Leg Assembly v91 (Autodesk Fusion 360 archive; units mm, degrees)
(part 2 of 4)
sketch "Sketch25" plane through (0, 0, 1.008) normal (0, 0, 1) x axis (-1, 0, 0)
  line L1 (-20.0076, 9.3042) -> (-16.55, 9.3042)
  line L2 (-20.0076, 2.9542) -> (-20.0076, 9.3042)
  line L3 (-16.55, 2.9542) -> (-20.0076, 2.9542)
  line L4 (-20.0076, -11.4458) -> (-17.255, -11.4458)
  line L5 (-20.0076, -17.7958) -> (-20.0076, -11.4458)
  line L6 (-17.255, -17.7958) -> (-20.0076, -17.7958)
  line L7 (-3.4928, -22.1208) -> (-13.668, -22.1208)
  line L8 (0.1537, -18.4744) -> (-3.4928, -22.1208)
  line L9 (0.1537, -10.7673) -> (0.1537, -18.4744)
  line L10 (-3.4928, -7.1208) -> (0.1537, -10.7673)
  line L11 (-13.668, -7.1208) -> (-3.4928, -7.1208)
  line L12 (-20.0076, -17.7958) -> (-17.255, -17.7958)
  line L13 (-20.0076, -11.4458) -> (-20.0076, -17.7958)
  line L14 (-17.255, -11.4458) -> (-20.0076, -11.4458)
  line L15 (-17.255, -17.7958) -> (-17.255, -11.4458)
  line L16 (-20.0076, 2.9542) -> (-16.55, 2.9542)
  line L17 (-20.0076, 9.3042) -> (-20.0076, 2.9542)
  line L18 (-16.55, 9.3042) -> (-20.0076, 9.3042)
  line L19 (-16.55, 2.9542) -> (-16.55, 9.3042)
  arc A1 centre (-8.3963, 6.1292) radius 8.75 clockwise from (-16.55, 9.3042) to (-16.55, 2.9542)
  arc A2 centre (-9.026, -14.6208) radius 8.8203 clockwise from (-17.255, -11.4458) to (-13.668, -7.1208)
  arc A3 centre (-9.026, -14.6208) radius 8.8203 clockwise from (-13.668, -22.1208) to (-17.255, -17.7958)
  point P10 (-20.0076, -11.4458)
  point P20 (-20.0076, -11.4458)
  point P12 (-17.255, -17.7958)
  point P18 (-17.255, -17.7958)
  point P5 (-20.0076, 9.3042)
  point P24 (-20.0076, 9.3042)
  point P2 (-16.55, 2.9542)
  point P22 (-16.55, 2.9542)
  horizontal L12
  vertical L13
  horizontal L14
  vertical L15
  coincident P10 P20
  coincident P12 P18
  horizontal L16
  vertical L17
  horizontal L18
  vertical L19
  coincident P5 P24
  coincident P2 P22
extrude "Extrude10" cut sketch "Sketch25" profile of L1 L2 L3 L16 L17 L18 L19 against normal blind 8.89
extrude "Extrude11" cut sketch "Sketch25" profile of L4 L5 L6 L12 L13 L14 L15 distance 11.43
copy_paste "CutPaste1"
remove_instance "RemoveInstance8"
remove_instance "RemoveInstance9"
mirror_component "MirrorComponent2"
derived_instance "DerivedInstance2"
position "Position4"
position "Position5"
position "Position6"
position "Position7"
sketch "main sketch" plane through (0, -27.2, 0) normal (0, -1, 0) x axis (1, 0, 0)
  line L1 (-18.7031, 75.8108) -> (12.2732, 75.8108)
  line L2 (-3.2149, -51.1892) -> (-3.2149, 75.8108)
  line L3 (-52.3824, 37.6979) -> (-20.6556, 77.3722)
  line L4 (-16.7506, 74.2495) -> (-48.4774, 34.5752)
  line L5 (-50.4299, 36.1365) -> (-18.7031, 75.8108)
  line L6 (-5.3332, -40.5169) -> (-52.5482, 34.8088)
  line L7 (-48.3116, 37.4643) -> (-1.0967, -37.8614)
  line L8 (-3.2149, -39.1892) -> (-50.4299, 36.1365)
  line L9 (-51.9387, 49.1154) -> (-56.8979, 53.0812)
  line L10 (-25.9057, 52.0131) -> (-51.9387, 49.1154)
  line L11 (-130.2149, -51.1892) -> (-130.2149, 75.8108)
  line L12 (-130.2149, 75.8108) -> (-3.2149, 75.8108)
  line L13 (-130.2149, -51.1892) -> (-3.2149, -51.1892)
  line L14 (42.0475, 34.5752) -> (10.3208, 74.2495)
  line L15 (14.2257, 77.3722) -> (45.9525, 37.6979)
  line L16 (44, 36.1365) -> (12.2732, 75.8108)
  line L17 (-5.3332, -37.8614) -> (41.8817, 37.4643)
  line L18 (46.1183, 34.8088) -> (-1.0967, -40.5169)
  line L19 (-3.2149, -39.1892) -> (44, 36.1365)
  line L20 (45.5088, 49.1154) -> (19.4758, 52.0131)
  line L21 (50.4681, 53.0812) -> (45.5088, 49.1154)
  circle C1 centre (12.2732, 75.8108) radius 1.5
  circle C2 centre (-18.7031, 75.8108) radius 1.5
  circle C3 centre (-18.7031, 75.8108) radius 14
  circle C4 centre (-50.4299, 36.1365) radius 11.5
  arc A1 centre (-50.4299, 36.1365) radius 2.5 clockwise from (-48.4774, 34.5752) to (-52.3824, 37.6979)
  arc A2 centre (-18.7031, 75.8108) radius 2.5 clockwise from (-20.6556, 77.3722) to (-16.7506, 74.2495)
  arc A3 centre (12.7387, 22.1428) radius 76.2 clockwise from (-61.6577, 38.6238) to (-25.78, 87.8905)
  arc A4 centre (29.1955, -0.6206) radius 76.2 clockwise from (-39.9887, 31.3166) to (-11.2687, 63.9479)
  arc A5 centre (-3.2149, -39.1892) radius 2.5 clockwise from (-1.0967, -37.8614) to (-5.3332, -40.5169)
  arc A6 centre (-50.4299, 36.1365) radius 2.5 clockwise from (-52.5482, 34.8088) to (-48.3116, 37.4643)
  circle C5 centre (-3.2149, -39.1892) radius 9
  arc A7 centre (129.3236, 102.7516) radius 203.2 clockwise from (-9.3573, -45.7673) to (-61.2132, 32.1403)
  arc A8 centre (153.1884, 104.2222) radius 203.2 clockwise from (3.4186, -33.1067) to (-39.5235, 39.7834)
  circle C6 centre (12.2732, 75.8108) radius 14
  circle C7 centre (44, 36.1365) radius 11.5
  arc A9 centre (44, 36.1365) radius 2.5 clockwise from (45.9525, 37.6979) to (42.0475, 34.5752)
  arc A10 centre (12.2732, 75.8108) radius 2.5 clockwise from (10.3208, 74.2495) to (14.2257, 77.3722)
  arc A11 centre (-3.2149, -39.1892) radius 2.5 clockwise from (-1.0967, -40.5169) to (-5.3332, -37.8614)
  arc A12 centre (44, 36.1365) radius 2.5 clockwise from (41.8817, 37.4643) to (46.1183, 34.8088)
  arc A13 centre (-19.1685, 22.1428) radius 76.2 clockwise from (19.3502, 87.8905) to (55.2278, 38.6238)
  arc A14 centre (-35.6254, -0.6206) radius 76.2 clockwise from (4.8389, 63.9479) to (33.5588, 31.3166)
  arc A15 centre (-135.7535, 102.7516) radius 203.2 clockwise from (54.7833, 32.1403) to (2.9274, -45.7673)
  arc A16 centre (-159.6183, 104.2222) radius 203.2 clockwise from (33.0936, 39.7834) to (-9.8485, -33.1067)
  point P2 (12.2732, 75.8108)
  point P5 (12.2732, 75.8108)
  point P4 (-18.7031, 75.8108)
  point P6 (-18.7031, 75.8108)
  point P7 (-3.2149, 75.8108)
  point P14 (-18.7031, 75.8108)
  point P9 (-50.4299, 36.1365)
  point P15 (-50.4299, 36.1365)
  point P20 (-39.9887, 31.3166)
  point P19 (-11.2687, 63.9479)
  point P17 (-25.78, 87.8905)
  point P16 (-61.6577, 38.6238)
  point P26 (-50.4299, 36.1365)
  point P30 (-9.3573, -45.7673)
  point P29 (-61.2132, 32.1403)
  point P33 (3.4186, -33.1067)
  point P32 (-39.5235, 39.7834)
  point P35 (-56.8979, 53.0812)
  point P37 (-25.9057, 52.0131)
  point P40 (-130.2149, 75.8108)
  point P38 (-130.2149, 75.8108)
  point P41 (-130.2149, -51.1892)
  point P39 (-130.2149, -51.1892)
  point P48 (12.2732, 75.8108)
  point P27 (-3.2149, -39.1892)
  point P55 (-3.2149, -39.1892)
  point P49 (44, 36.1365)
  point P54 (44, 36.1365)
  point P43 (44, 36.1365)
  point P56 (19.3502, 87.8905)
  point P59 (4.8389, 63.9479)
  point P57 (55.2278, 38.6238)
  point P60 (33.5588, 31.3166)
  point P65 (33.0936, 39.7834)
  point P62 (54.7833, 32.1403)
  point P63 (2.9274, -45.7673)
  point P66 (-9.8485, -33.1067)
  point P68 (19.4758, 52.0131)
  point P70 (50.4681, 53.0812)
  point P36 (-51.9387, 49.1154)
  point P28 (-3.2149, -39.1892)
  point P69 (45.5088, 49.1154)
  concentric C2 C3
  coincident P2 P5
  coincident P4 P6
  midpoint L1 P7
  perpendicular L1 L2
  tangent L3 A1
  tangent A1 L4
  parallel L3 L4
  tangent L4 A2
  tangent L3 A2
  coincident P4 P14
  coincident P9 P15
  tangent C3 A3
  tangent C4 A3
  coincident C4 P20
  coincident C3 P19
  tangent C3 A4
  tangent C4 A4
  coincident C3 P17
  coincident C4 P16
  tangent L6 A5
  tangent A5 L7
  parallel L6 L7
  tangent L7 A6
  tangent L6 A6
  coincident P9 P26
  concentric A5 C5
  coincident C5 P30
  coincident C4 P29
  coincident C5 P33
  coincident C4 P32
  tangent C5 A8
  tangent C5 A7
  tangent C4 A8
  tangent C4 A7
  coincident A3 P35
  coincident A4 P37
  parallel L2 L11
  coincident L11 P40
  perpendicular L11 L12
  coincident P38 L12
  coincident L11 P41
  perpendicular L11 L13
  coincident P39 P41
  concentric C1 C6
  tangent L14 A9
  tangent A9 L15
  parallel L14 L15
  tangent L15 A10
  tangent L14 A10
  coincident P2 P48
  tangent L17 A11
  tangent A11 L18
  parallel L17 L18
  tangent L18 A12
  tangent L17 A12
  coincident P27 P55
  coincident P49 P54
  coincident P43 P54
  tangent C6 A13
  tangent C7 A13
  tangent C7 A14
  tangent C6 A14
  coincident C6 P56
  coincident C6 P59
  coincident C7 P57
  coincident C7 P60
  tangent C7 A16
  tangent C5 A16
  tangent C5 A15
  tangent C7 A15
  coincident C7 P65
  coincident C7 P62
  coincident C5 P63
  coincident C5 P66
  coincident A14 P68
  coincident A13 P70
  dimension "d55" distance L3 L4 = 5
  dimension "d57" distance P14 P15 = 50.8
  dimension "d58" radius A3 = 76.2
  dimension "d69" radius A4 = 76.2 (= "d58")
  dimension "d123" diameter C3 = 28
  dimension "d124" diameter C4 = 23
  dimension "d125" distance P26 P27 = 88.9
  dimension "d126" distance L6 L7 = 5 (= "d55")
  dimension "d127" diameter C5 = 18
  dimension "d128" radius A7 = 203.2 (= "d129")
  dimension "d129" radius A8 = 203.2
  dimension "d142" distance P35 P36 = 6.35
  dimension "d143" angle L9 L10 = 135
  dimension "d144" angle L5 L9 = 90
  dimension "d145" distance P36 P37 = 26.1938 (= "1 in + ( ( 1 / 32 ) * 1 in )")
  dimension "d146" distance P7 P40 = 127
  dimension "d147" distance P28 L11 = 127 (= "5 in + X")
  dimension "d186" distance P28 L12 = 115 (= "Linear Dimension-10")
  dimension "d201" distance P38 P39 = 127
  dimension "d230" distance L14 L15 = 5
  dimension "d231" diameter A11 = 5
  dimension "d232" distance P54 P55 = 88.9 (= "d125")
  dimension "d233" distance P48 P49 = 50.8 (= "d57")
  dimension "d234" diameter C7 = 23 (= "d124")
  dimension "d235" diameter C6 = 28 (= "d123")
  dimension "d236" radius A13 = 76.2 (= "d58")
  dimension "d237" radius A14 = 76.2 (= "d58")
  dimension "d238" radius A15 = 203.2 (= "d128")
  dimension "d239" radius A16 = 203.2 (= "d128")
  dimension "d245" angle L20 L21 = 135 (= "d143")
  dimension "d246" angle L16 L21 = 90 (= "d144")
  dimension "d247" distance P69 P70 = 6.35 (= "d142")
  dimension "d248" distance P68 P69 = 26.1938 (= "d145")
work_plane "WorkPlane1" PathDistance 0.5
copy_paste "CutPaste1"
copy_paste "CutPaste2"
copy_paste "CutPaste1"
extrude "Extrude1" new body sketch "main sketch" profile of C3 C4 A3 A4 A8 L9 L10 along normal blind 20.05 (= "0.75 in + gapfit1")
extrude "Extrude3" new body sketch "main sketch" profile of C4 A4 C5 A7 A8 A16 blind 6.35 from offset 6.85 (= "( 0.5 in + gapfit1 ) / 2")
extrude "Extrude4" new body sketch "main sketch" profile of C6 C7 A13 A14 A16 L20 L21 along normal blind 20.05 (= "0.75 in + gapfit1")
extrude "Extrude5" new body sketch "main sketch" profile of C5 A8 C7 A14 A15 A16 blind 6.35 from offset 6.85 (= "( 0.5 in + gapfit1 ) / 2")
extrude "Extrude6" cut sketch "main sketch" profile of C4 A3 A4 A8 L9 L10 C7 A13 A14 A16 L20 L21 blind 6.35 from offset 6.85 (= "( 0.5 in + gapfit1 ) / 2")
work_plane "WorkPlane3" AlongDistance 6.85 (= "0.25 in + gapfit2")
align "Align5"
align "Align6"
sketch "Sketch12" plane through (0, -20.35, 0) normal (0, 1, 0) x axis (-1, 0, 0)
  arc A1 centre (-12.7387, 22.1428) radius 76.2 clockwise from (25.78, 87.8905) to (61.6577, 38.6238)
  arc A2 centre (18.7031, 75.8108) radius 14 clockwise from (11.2687, 63.9479) to (25.78, 87.8905)
  arc A3 centre (-29.1955, -0.6206) radius 76.2 clockwise from (11.2687, 63.9479) to (39.9887, 31.3166)
  arc A4 centre (50.4299, 36.1365) radius 11.5 clockwise from (61.6577, 38.6238) to (39.9887, 31.3166)
  circle C1 centre (18.7031, 75.8108) radius 14
  point P3 (25.78, 87.8905)
  concentric A2 C1
  coincident P3 C1
extrude "Extrude31" cut sketch "Sketch12" profile of A2 C1 against normal blind 6.85 (magnitude of "-0.25 in - gapfit2")
fillet "Fillet2" radius 3.175
extrude "Extrude21" cut of existing geometry blind -0.5 (= "-gapfit1 / 2")
extrude "Extrude22" cut of existing geometry blind -0.5 (= "-gapfit1 / 2")
extrude "Extrude23" cut of existing geometry blind -0.5 (= "-gapfit1 / 2")
extrude "Extrude24" cut of existing geometry blind -0.5 (= "-gapfit1 / 2")
component_from_bodies "Body->Comp1"
component_from_bodies "Body->Comp2"
component_from_bodies "Body->Comp3"
component_from_bodies "Body->Comp4"
copy_paste "CutPaste1"
copy_paste "CutPaste2"
copy_paste "CutPaste3"
copy_paste "CutPaste4"
sketch "Sketch10" plane through (0, -33.55, 0) normal (0, -1, 0) x axis (1, 0, 0)
  line L1 (-3.2149, -39.1892) -> (-50.4299, 36.1365)
  line L2 (-3.2149, -39.1892) -> (44, 36.1365)
  line L3 (-22.3639, -32.4561) -> (-5.9307, -22.1556)
  line L4 (-0.4992, -22.1556) -> (15.9341, -32.4561)
  line L5 (-54.0229, 15.1486) -> (-34.8377, 27.1741)
  line L6 (47.593, 15.1486) -> (28.4078, 27.1741)
  line L7 (-28.622, 4.84) -> (-50.611, 17.2872)
  line L8 (-32.9107, -12.8368) -> (-28.622, 4.84)
  line L9 (-16.9311, -14.0621) -> (-32.9107, -12.8368)
  line L10 (-18.9252, -30.3007) -> (-16.9311, -14.0621)
  line L11 (22.1921, 4.84) -> (44.1811, 17.2872)
  line L12 (26.4808, -12.8368) -> (22.1921, 4.84)
  line L13 (10.5012, -14.0621) -> (26.4808, -12.8368)
  line L14 (12.4954, -30.3007) -> (10.5012, -14.0621)
  arc A1 centre (153.1884, 104.2222) radius 203.2 clockwise from (3.4186, -33.1067) to (-39.5235, 39.7834)
  arc A2 centre (129.3236, 102.7516) radius 203.2 clockwise from (-9.3573, -45.7673) to (-61.2132, 32.1403)
  circle C1 centre (-50.4299, 36.1365) radius 11.5
  circle C2 centre (-3.2149, -39.1892) radius 9
  arc A3 centre (-135.7535, 102.7516) radius 203.2 clockwise from (54.7833, 32.1403) to (2.9274, -45.7673)
  arc A4 centre (-159.6183, 104.2222) radius 203.2 clockwise from (33.0936, 39.7834) to (-9.8485, -33.1067)
  circle C3 centre (44, 36.1365) radius 11.5
  arc A5 centre (153.1884, 104.2222) radius 207.2 clockwise from (0.4703, -35.81) to (-43.317, 38.5149)
  arc A6 centre (129.3236, 102.7516) radius 199.2 clockwise from (-6.6274, -42.8437) to (-57.4625, 33.5303)
  arc A7 centre (-159.6183, 104.2222) radius 207.2 clockwise from (36.8871, 38.5149) to (-6.9002, -35.81)
  arc A8 centre (-135.7535, 102.7516) radius 199.2 clockwise from (51.0326, 33.5303) to (0.1975, -42.8437)
  point P21 (-5.9307, -22.1556)
  point P22 (-22.3639, -32.4561)
  point P23 (15.9341, -32.4561)
  point P24 (-0.4992, -22.1556)
  point P25 (-34.8377, 27.1741)
  point P26 (-54.0229, 15.1486)
  point P27 (28.4078, 27.1741)
  point P28 (47.593, 15.1486)
  point P41 (-50.611, 17.2872)
  point P42 (-28.622, 4.84)
  point P43 (-32.9107, -12.8368)
  point P44 (-16.9311, -14.0621)
  point P45 (-18.9252, -30.3007)
  point P46 (44.1811, 17.2872)
  point P47 (22.1921, 4.84)
  point P48 (26.4808, -12.8368)
  point P49 (10.5012, -14.0621)
  point P50 (12.4954, -30.3007)
  point P18 (-3.2149, -39.1892)
  point P20 (-3.2149, -39.1892)
  point P8 (-50.4299, 36.1365)
  point P16 (44, 36.1365)
  coincident A1 P21
  coincident A2 P22
  perpendicular L1 L3
  coincident A3 P23
  coincident A4 P24
  perpendicular L2 L4
  coincident A1 P25
  coincident A2 P26
  coincident A4 P27
  coincident A3 P28
  perpendicular L2 L6
  perpendicular L1 L5
  coincident A6 P41
  coincident L5 P41
  coincident A5 P42
  coincident A6 P43
  coincident A5 P44
  coincident L3 P45
  coincident A6 P45
  coincident L6 P46
  coincident A8 P46
  coincident A7 P47
  coincident A8 P48
  coincident A7 P49
  coincident A8 P50
  coincident L4 P50
  dimension "d338" distance P18 L3 = 15.875
  dimension "d339" distance P20 L4 = 15.875 (= "d338")
  dimension "d340" distance P8 L5 = 15.875
  dimension "d341" distance P16 L6 = 15.875 (= "d340")
  dimension "d342" = 4
  dimension "d343" = -4
  dimension "d344" = 4
  dimension "d345" = -4
  dimension "d346" distance L5 P42 = 22.225
  dimension "d347" distance L5 P43 = 34.925
  dimension "d348" distance L5 P44 = 44.45
  dimension "d349" distance L6 P47 = 22.225 (= "d346")
  dimension "d350" distance L6 P48 = 34.925 (= "d347")
  dimension "d351" distance L6 P49 = 44.45 (= "d348")
extrude "Extrude1" cut sketch "Sketch10" profile of L3 L4 L5 L6 A5 A6 A7 A8 L7 L8 L9 L10 L11 L12 L13 L14 distance -119.38
web "Web1" Thickness 4
sketch "Sketch11" plane through (0, -40.4, 0) normal (0, -1, 0) x axis (1, 0, 0)
  line L1 (10.5012, -14.0621) -> (26.4808, -12.8368)
  line L2 (12.4954, -30.3007) -> (10.5012, -14.0621)
  line L3 (26.4808, -12.8368) -> (22.1921, 4.84)
  line L4 (22.1921, 4.84) -> (44.1811, 17.2872)
  line L5 (44.1811, 17.2872) -> (31.8462, 25.0189)
  line L6 (2.9107, -24.293) -> (12.4954, -30.3007)
  arc A1 centre (-135.7535, 102.7516) radius 203.2 clockwise from (54.7833, 32.1403) to (2.9274, -45.7673)
  arc A2 centre (44, 36.1365) radius 11.5 clockwise from (33.0936, 39.7834) to (54.7833, 32.1403)
  arc A3 centre (-159.6183, 104.2222) radius 203.2 clockwise from (33.0936, 39.7834) to (-9.8485, -33.1067)
  arc A4 centre (-3.2149, -39.1892) radius 9 clockwise from (2.9274, -45.7673) to (-9.8485, -33.1067)
  arc A5 centre (-135.7535, 102.7516) radius 199.2 clockwise from (44.1811, 17.2872) to (12.4954, -30.3007)
  arc A6 centre (-159.6183, 104.2222) radius 207.2 clockwise from (31.8462, 25.0189) to (2.9107, -24.293)
web "Web1" Thickness 4
fillet "Fillet2" radius 1.5
chamfer "Chamfer1" distance 1.5875 (= "( 1 / 16 ) * 1 in")
sketch "Sketch13" plane through (0, 24.8582, 0) normal (0, 1, 0) x axis (-1, 0, 0)
  line L1 (37.9202, 66.7891) -> (25.2712, 55.623)
  line L2 (3.0497, 111.0882) -> (38.1993, 71.2706)
  line L3 (-14.0808, 100.2011) -> (-1.4317, 111.3672)
  line L4 (40.3005, 68.8903) -> (0.9485, 113.4684)
  line L5 (5.4814, 38.1532) -> (40.3005, 68.8903)
  line L6 (-33.8706, 82.7314) -> (5.4814, 38.1532)
  line L7 (0.9485, 113.4684) -> (-33.8706, 82.7314)
  line L8 (38.1993, 71.2706) -> (3.0497, 111.0882)
  line L9 (-1.4317, 111.3672) -> (-14.0808, 100.2011)
  line L10 (25.2712, 55.623) -> (37.9202, 66.7891)
  line L11 (-31.7694, 80.3511) -> (3.3802, 40.5335)
  line L12 (7.8616, 40.2544) -> (20.5107, 51.4206)
  line L13 (-18.8413, 95.9987) -> (-31.4904, 84.8326)
  line L14 (-34.5763, 82.7753) -> (5.4374, 37.4475)
  line L15 (0.9924, 114.1742) -> (-34.5763, 82.7753)
  line L16 (41.0062, 68.8464) -> (0.9924, 114.1742)
  line L17 (5.4374, 37.4475) -> (41.0062, 68.8464)
  line L18 (1.411, 120.8964) -> (-41.2985, 83.1939)
  line L19 (47.7284, 68.4278) -> (1.411, 120.8964)
  line L20 (5.0189, 30.7253) -> (47.7284, 68.4278)
  line L21 (-41.2985, 83.1939) -> (5.0189, 30.7253)
  line L22 (47.7284, 68.4278) -> (1.411, 120.8964)
  line L23 (57.2494, 76.8326) -> (47.7284, 68.4278)
  line L24 (10.932, 129.3012) -> (57.2494, 76.8326)
  line L25 (1.411, 120.8964) -> (10.932, 129.3012)
  line L26 (5.0189, 30.7253) -> (-41.2985, 83.1939)
  line L27 (-4.5021, 22.3205) -> (5.0189, 30.7253)
  line L28 (-50.8195, 74.7891) -> (-4.5021, 22.3205)
  line L29 (-41.2985, 83.1939) -> (-50.8195, 74.7891)
  arc A1 centre (-11.9796, 97.8209) radius 3.175 clockwise from (-14.3599, 95.7197) to (-14.0808, 100.2011)
  arc A2 centre (23.17, 58.0032) radius 3.175 clockwise from (25.2712, 55.623) to (20.7897, 55.902)
  point P19 (-1.4317, 111.3672)
  point P26 (-31.4904, 84.8326)
  point P6 (25.2712, 55.623)
  point P22 (3.3802, 40.5335)
  point P17 (38.1993, 71.2706)
  perpendicular L4 L5
  parallel L4 L6
  parallel L5 L7
  coincident L7 P19
  coincident L7 P26
  coincident P6 L5
  coincident L6 P22
  coincident L4 P17
  perpendicular L22 L23
  parallel L22 L24
  parallel L23 L25
  perpendicular L26 L27
  parallel L26 L28
  parallel L27 L29
  dimension "d373" = -0.5 (= "-gapfit3")
  dimension "d374" = -5.2625 (= "-gapfit3 - 0.1875 in")
  dimension "d394" distance L22 L24 = 12.7
  dimension "d395" distance L21 L28 = 12.7
extrude "Extrude32" new body sketch "Sketch13" profile of L14 L15 L16 L17 L18 L19 L20 L21 against normal blind 32.8676
fillet "Fillet3" radius 3.675 (= "0.125 in + gapfit3")
copy_paste_bodies "CutPasteBodies1"
component_from_bodies "Body->Comp1"
fillet "Fillet1" radius 8.4375 (= "0.125 in + 0.1875 in + gapfit3")
sketch "Sketch14" plane through (-18.0647, 0, 15.9469) normal (0.7497, 0, -0.6618) x axis (0, 1, 0)
  line L1 (16.8832, 68.1316) -> (16.8832, 61.7816)
  line L2 (18.032, 47.6316) -> (18.032, 41.2816)
  line L3 (14.8582, 41.2816) -> (18.032, 41.2816)
  line L4 (16.8832, 68.1316) -> (14.8582, 68.1316)
  line L5 (20.0319, 70.1316) -> (-8.0094, 70.1316)
  line L6 (20.0319, 39.2816) -> (20.0319, 70.1316)
  line L7 (-8.0094, 39.2816) -> (20.0319, 39.2816)
  line L8 (-8.0094, 70.1316) -> (-8.0094, 39.2816)
  line L9 (-8.0094, 81.2628) -> (-8.0094, 28.1503)
  horizontal L5
  vertical L6
  horizontal L7
  vertical L8
  collinear L8 L9
  dimension "d385" distance L2 L6 = 2
  dimension "d386" distance L4 L5 = 2
  dimension "d387" distance L3 L7 = 2
copy_paste "CutPaste4"
extrude "Extrude1" cut sketch "Sketch14" profile of L5 L6 L7 L8 against normal blind 91.44
sketch "Sketch15" plane through (59.3633, 0, 67.247) normal (0.6618, 0, 0.7497) x axis (0, 1, 0)
  line L1 (-8.0094, 72.6289) -> (-8.0094, 32.5339)
  line L2 (20.032, 61.4977) -> (-8.0094, 61.4977)
  line L3 (20.032, 43.6652) -> (20.032, 61.4977)
  line L4 (-8.0094, 43.6652) -> (20.032, 43.6652)
  line L5 (-8.0094, 61.4977) -> (-8.0094, 43.6652)
  line L6 (24.8582, 24.0964) -> (-8.0094, 24.0964)
  line L7 (-8.0094, 81.0664) -> (24.8582, 81.0664)
  point P4 (-8.0094, 61.4977)
  point P5 (20.032, 61.4977)
  horizontal L2
  vertical L3
  horizontal L4
  vertical L5
  coincident L1 P4
  dimension "d401" distance P4 P5 = 28.0414
  dimension "d403" distance L4 L6 = 19.5688
  dimension "d404" distance L2 L7 = 19.5688
extrude "Extrude3" cut sketch "Sketch15" profile of L1 L2 L3 L4 L5 against normal blind 180.34
fillet "Fillet2" radius 3.175
extrude "Extrude2" add sketch "Sketch13" profile of L4 L5 L6 L7 L8 L9 L10 L12 L13 L14 L15 L16 L17 L18 L19 L20 L21 L22 L23 L24 L25 L26 L27 L28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 along normal blind 4.7625
fillet "Fillet4" radius 12.7
work_plane "WorkPlane8"
offset_faces "OffsetFaces1" distance -9.9385
sketch "Sketch16" plane through (0, 0, 0) normal (0, 1, 0) x axis (1, 0, 0)
  circle C1 centre (12.2732, -75.8108) radius 10
  circle C2 centre (12.2732, -75.8108) radius 1.5
  circle C3 centre (12.2732, -68.8108) radius 1.5
  circle C4 centre (12.2732, -82.8108) radius 1.5
  circle C5 centre (19.2732, -75.8108) radius 1.5
  circle C6 centre (5.2732, -75.8108) radius 1.5
  circle C7 centre (-18.7031, -75.8108) radius 10
  circle C8 centre (-18.7031, -75.8108) radius 1.5
  circle C9 centre (-25.7031, -75.8108) radius 1.5
  circle C10 centre (-11.7031, -75.8108) radius 1.5
  circle C11 centre (-18.7031, -82.8108) radius 1.5
  circle C12 centre (-18.7031, -68.8108) radius 1.5
base_feature "Base Feature1"
base_feature "Base Feature1"
hole "Hole4" HoleDepth 93.98 HoleDiameter 3.5 (= "m3_diam") TipAngle 180
align "Align1"
sketch "Sketch17" plane through (0, -47.25, 0) normal (0, -1, 0) x axis (1, 0, 0)
  line L1 (-25.7031, 79.2172) -> (-22.7531, 77.514)
  line L2 (-28.6531, 77.514) -> (-25.7031, 79.2172)
  line L3 (-28.6531, 74.1077) -> (-28.6531, 77.514)
  line L4 (-25.7031, 72.4045) -> (-28.6531, 74.1077)
  line L5 (-22.7531, 74.1077) -> (-25.7031, 72.4045)
  line L6 (-22.7531, 77.514) -> (-22.7531, 74.1077)
  line L7 (-25.7031, 79.2172) -> (-25.7031, 75.8108)
  line L8 (5.2732, 79.2172) -> (5.2732, 75.8108)
  line L9 (2.3232, 77.514) -> (5.2732, 79.2172)
  line L10 (2.3232, 74.1077) -> (2.3232, 77.514)
  line L11 (5.2732, 72.4045) -> (2.3232, 74.1077)
  line L12 (8.2232, 74.1077) -> (5.2732, 72.4045)
  line L13 (8.2232, 77.514) -> (8.2232, 74.1077)
  line L14 (5.2732, 79.2172) -> (8.2232, 77.514)
  circle C1 centre (12.2732, 82.8108) radius 1.75
  circle C2 centre (12.2732, 68.8108) radius 1.75
  circle C3 centre (19.2732, 75.8108) radius 1.75
  point P5 (-25.7031, 75.8108)
  point P13 (-25.7031, 75.8108)
  point P14 (-25.7031, 75.8108)
  point P8 (-25.7031, 79.2172)
  point P15 (-25.7031, 79.2172)
  point P6 (5.2732, 75.8108)
  point P16 (5.2732, 75.8108)
  point P24 (5.2732, 75.8108)
  point P17 (5.2732, 79.2172)
  point P18 (5.2732, 79.2172)
  coincident P5 P13
  coincident P5 P14
  vertical L7
  coincident P8 L7
  coincident P8 P15
  coincident P6 P16
  vertical L8
  coincident P16 P24
  coincident P17 P18
  dimension "d438" distance L3 L6 = 5.9 (= "m3_locknut_width")
  dimension "d439" distance L10 L13 = 5.9 (= "m3_locknut_width")
extrude "Extrude1" cut sketch "Sketch17" profile of L9 L10 L11 L12 L13 L14 against normal blind 4
extrude "Extrude1" sketch "Sketch17" profile of L1 L2 L3 L4 L5 L6 blind -4
circular_pattern "C-Pattern1" TotalAngle 360
circular_pattern "C-Pattern1" TotalAngle 360
align "Align1"
circular_pattern "C-Pattern1" TotalAngle 360
circular_pattern "C-Pattern2" TotalAngle 360
copy_paste_bodies "CopyPasteBodies1"
move "Move4"
align "Align7"
offset_faces "OffsetFaces3" distance 4
copy_paste_bodies "CopyPasteBodies2"
move "Move5"
align "Align8"
offset_faces "OffsetFaces6" distance 5
circular_pattern "C-Pattern1" TotalAngle 360
component_from_bodies "Body->Comp7"
copy_paste_bodies "CutPasteBodies1"
copy_paste_bodies "CutPasteBodies1"
copy_paste "CutPaste1"
extrude "Extrude5" add of existing geometry blind 1.5875 (= "( 1 / 16 ) * 1 in")
copy_paste_bodies "CopyPasteBodies3"
move "Move6"
align "Align9"
copy_paste_bodies "CopyPasteBodies4"
move "Move7"
align "Align10"
offset_faces "OffsetFaces4" distance 9
copy_paste_bodies "CutPasteBodies2"
component_from_bodies "Body->Comp8"
copy_paste "CutPaste2"
hole "Hole1" HoleDepth 93.98 HoleDiameter 3.5 (= "m3_diam") TipAngle 180
copy_paste_bodies "CopyPasteBodies5"
move "Move8"
align "Align11"
offset_faces "OffsetFaces5" distance 9
copy_paste_bodies "CopyPasteBodies6"
move "Move9"
align "Align12"
copy_paste_bodies "CopyPasteBodies7"
move "Move10"
align "Align13"
copy_paste_bodies "CopyPasteBodies8"
move "Move11"
align "Align14"
copy_paste_bodies "CutPasteBodies1"
copy_paste_bodies "CutPasteBodies2"
copy_paste_bodies "CutPasteBodies1"
copy_paste_bodies "CutPasteBodies2"
hole "Hole2" HoleDepth 93.98 HoleDiameter 3.5 (= "m3_diam") TipAngle 180
copy_paste_bodies "CopyPasteBodies9"
move "Move12"
copy_paste_bodies "CutPasteBodies1"
remove_instance "RemoveInstance1"
align "Align15"
copy_paste_bodies "CopyPasteBodies10"
move "Move13"
align "Align16"
offset_faces "OffsetFaces7" distance 4
copy_paste_bodies "CutPasteBodies3"
component_from_bodies "Body->Comp9"
copy_paste "CutPaste3"
sketch "Sketch18" plane through (0, 31.2082, 0) normal (0, 1, 0) x axis (-1, 0, 0)
  line L1 (19.3368, 119.7802) -> (48.8446, 86.3536)
  line L2 (-41.2985, 83.1939) -> (1.411, 120.8964)
  line L3 (-12.9069, 31.8415) -> (-42.4147, 65.2681)
  line L4 (47.7284, 68.4278) -> (5.0189, 30.7253)
  line L5 (47.7284, 68.4278) -> (1.411, 120.8964)
  line L6 (10.932, 129.3012) -> (57.2494, 76.8326)
  line L7 (57.2494, 76.8326) -> (47.7284, 68.4278)
  line L8 (1.411, 120.8964) -> (10.932, 129.3012)
  line L9 (-50.8195, 74.7891) -> (-4.5021, 22.3205)
  line L10 (-41.2985, 83.1939) -> (-50.8195, 74.7891)
  line L11 (-41.2985, 83.1939) -> (5.0189, 30.7253)
  line L12 (-4.5021, 22.3205) -> (5.0189, 30.7253)
  line L13 (6.1715, 125.0988) -> (52.4889, 72.6302)
  arc A1 centre (39.3236, 77.9488) radius 12.7 clockwise from (48.8446, 86.3536) to (47.7284, 68.4278)
  arc A2 centre (9.8158, 111.3754) radius 12.7 clockwise from (1.411, 120.8964) to (19.3368, 119.7802)
  arc A3 centre (-32.8937, 73.6729) radius 12.7 clockwise from (-42.4147, 65.2681) to (-41.2985, 83.1939)
  arc A4 centre (-3.3859, 40.2463) radius 12.7 clockwise from (5.0189, 30.7253) to (-12.9069, 31.8415)
  circle C1 centre (7.2492, 46.2916) radius 1.5
  circle C2 centre (14.5961, 52.7772) radius 1.5
  circle C3 centre (24.6588, 61.6601) radius 1.5
  circle C4 centre (32.0057, 68.1457) radius 1.5
  circle C5 centre (-0.8193, 105.3301) radius 1.5
  circle C6 centre (-8.1663, 98.8445) radius 1.5
  circle C7 centre (-18.2289, 89.9616) radius 1.5
  circle C8 centre (-25.5758, 83.476) radius 1.5
  point P38 (52.4889, 72.6302)
  point P39 (6.1715, 125.0988)
  point P40 (41.9374, 84.583)
  point P41 (16.723, 113.146)
  midpoint L7 P38
  midpoint L8 P39
  coincident L13 P40
  coincident L13 P41
  dimension "d480" distance P40 P41 = 38.1
  dimension "d481" distance L8 P41 = 15.9438 (= "( 2.7554133858267762 in - d480 ) / 2")
hole "Hole1" HoleDepth 93.98 HoleDiameter 3.5 (= "m3_diam") TipAngle 180
work_plane "WorkPlane9"
mirror "Mirror1" mirrorStitchTolerance 0.1016
copy_paste_bodies "CopyPasteBodies11"
move "Move14"
offset_faces "OffsetFaces8" distance -15
align "Align18"
copy_paste_bodies "CopyPasteBodies12"
move "Move15"
copy_paste_bodies "CopyPasteBodies13"
move "Move16"
copy_paste_bodies "CopyPasteBodies14"
move "Move17"
copy_paste_bodies "CopyPasteBodies15"
move "Move18"
align "Align19"
align "Align20"
align "Align21"
align "Align22"
component_from_bodies "Body->Comp10"
copy_paste "CutPaste4"
remove_body "RemoveBody36"
copy_paste_bodies "CutPasteBodies2"
mirror "Mirror2" mirrorStitchTolerance 0.1016
copy_paste "CutPaste5"
sketch "Sketch1" plane through (0, -40.4, 0) normal (0, -1, 0) x axis (1, 0, 0)
  line L1 (-22.1095, 68.8108) -> (-20.4063, 65.8608)
  line L2 (-20.4063, 71.7608) -> (-22.1095, 68.8108)
  line L3 (-16.9999, 71.7608) -> (-20.4063, 71.7608)
  line L4 (-15.2968, 68.8108) -> (-16.9999, 71.7608)
  line L5 (-16.9999, 65.8608) -> (-15.2968, 68.8108)
  line L6 (-20.4063, 65.8608) -> (-16.9999, 65.8608)
  line L7 (-11.7031, 72.4045) -> (-8.7531, 74.1077)
  line L8 (-14.6531, 74.1077) -> (-11.7031, 72.4045)
  line L9 (-14.6531, 77.514) -> (-14.6531, 74.1077)
  line L10 (-11.7031, 79.2172) -> (-14.6531, 77.514)
  line L11 (-8.7531, 77.514) -> (-11.7031, 79.2172)
  line L12 (-8.7531, 74.1077) -> (-8.7531, 77.514)
  line L13 (-15.2968, 82.8108) -> (-16.9999, 85.7608)
  line L14 (-16.9999, 79.8608) -> (-15.2968, 82.8108)
  line L15 (-20.4063, 79.8608) -> (-16.9999, 79.8608)
  line L16 (-22.1095, 82.8108) -> (-20.4063, 79.8608)
  line L17 (-20.4063, 85.7608) -> (-22.1095, 82.8108)
  line L18 (-16.9999, 85.7608) -> (-20.4063, 85.7608)
  line L19 (-25.7031, 79.2172) -> (-28.6531, 77.514)
  line L20 (-22.7531, 77.514) -> (-25.7031, 79.2172)
  line L21 (-22.7531, 74.1077) -> (-22.7531, 77.514)
  line L22 (-25.7031, 72.4045) -> (-22.7531, 74.1077)
  line L23 (-28.6531, 74.1077) -> (-25.7031, 72.4045)
  line L24 (-28.6531, 77.514) -> (-28.6531, 74.1077)
  line L25 (31.5525, 35.3457) -> (-37.9823, 35.3457)
  line L26 (-37.9823, 9.9457) -> (31.5525, 9.9457)
  line L27 (-37.9823, 60.7457) -> (-37.9823, 9.9457)
  line L28 (31.5525, 60.7457) -> (-37.9823, 60.7457)
  line L29 (31.5525, 9.9457) -> (31.5525, 60.7457)
  line L30 (-37.9823, 60.7457) -> (31.5525, 9.9457)
  line L31 (31.5525, 60.7457) -> (-37.9823, 9.9457)
  circle C1 centre (-50.4299, 36.1365) radius 1.75
  circle C2 centre (-18.7031, 75.8108) radius 1.75
  arc A1 centre (-18.7031, 75.8108) radius 12.4125 clockwise from (-24.9776, 86.5207) to (-12.1117, 65.293)
  arc A2 centre (12.7387, 22.1428) radius 74.6125 clockwise from (-60.1078, 38.2805) to (-24.9776, 86.5207)
  arc A3 centre (-50.4299, 36.1365) radius 9.9125 clockwise from (-41.43, 31.982) to (-60.1078, 38.2805)
  arc A4 centre (29.1955, -0.6206) radius 77.7875 clockwise from (-41.43, 31.982) to (-12.1117, 65.293)
  arc A5 centre (153.1884, 104.2222) radius 203.2 clockwise from (3.4186, -33.1067) to (-39.5235, 39.7834)
  arc A6 centre (-159.6183, 104.2222) radius 203.2 clockwise from (33.0936, 39.7834) to (-9.8485, -33.1067)
  arc A7 centre (-35.6254, -0.6206) radius 76.2 clockwise from (4.8389, 63.9479) to (33.5588, 31.3166)
  arc A8 centre (29.1955, -0.6206) radius 76.2 clockwise from (-39.9887, 31.3166) to (-11.2687, 63.9479)
  point P47 (31.5525, 35.3457)
  point P46 (-37.9823, 35.3457)
  point P52 (-3.2149, 35.3457)
  coincident A6 P47
  coincident A7 P47
  coincident A5 P46
  coincident A8 P46
  horizontal L26
  perpendicular L26 L27
  parallel L26 L28
  parallel L27 L29
  coincident L30 P52
  coincident L31 P52
  midpoint L25 P52
  coincident P47 L29
  dimension "d494" distance L26 L28 = 50.8
extrude "Extrude1" new body sketch "Sketch1" profile of A5 A6 A7 A8 L26 L28 against normal blind 19.05 and along normal blind 6.85
component_from_bodies "Body->Comp2"
as_built_joint "As-built1"
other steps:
base_feature "Base Feature1"
base_feature "Base Feature1"
base_feature "Base Feature1"
base_feature "Base Feature1"
base_feature "Base Feature1"
base_feature "Base Feature1"
base_feature "Base Feature1"
derived_base_feature "Derived Base Feature"
base_feature "Base Feature1"
base_feature "Base Feature3"
base_feature "Base Feature1"
base_feature "Base Feature2"
base_feature "Base Feature2"
base_feature "Base Feature3"
base_feature "Base Feature1"
base_feature "Base Feature1"
base_feature "Base Feature2"
base_feature "Base Feature3"
base_feature "Base Feature1"
base_feature "Base Feature2"
base_feature "Base Feature3"
base_feature "Base Feature1"
base_feature "Base Feature2"
base_feature "Base Feature2"
base_feature "Base Feature3"
base_feature "Base Feature4"
base_feature "Base Feature1"
base_feature "Base Feature1"
extrude "Extrude1" cut sketch "Sketch10" profile of L3 L4 L5 L6 A5 A6 A7 A8 L7 L8 L9 L10 L11 L12 L13 L14 distance -119.38
fillet "Fillet2" radius 1.5
base_feature "Base Feature1"
hole "Hole1" HoleDepth 93.98 HoleDiameter 3.5 (= "m3_diam") TipAngle 180
hole "Hole2" HoleDepth 93.98 HoleDiameter 3.5 (= "m3_diam") TipAngle 180
base_feature "Base Feature1"
delete_face "DeleteFace5"
delete_face "DeleteFace6"
delete_face "DeleteFace7"
base_feature "Base Feature1"
base_feature "Base Feature2"
base_feature "Base Feature3"
offset_faces "OffsetFaces1" distance -3.175
chamfer "Chamfer1" distance 4.7625
base_feature "Base Feature1"
chamfer "Chamfer1" distance 1.5875 (= "( 1 / 16 ) * 1 in")
hole "Hole4" HoleDepth 93.98 HoleDiameter 3.5 (= "m3_diam") TipAngle 180
hole "Hole5" HoleDepth 93.98 HoleDiameter 3.5 (= "m3_diam") TipAngle 180
base_feature "Base Feature1"
hole "Hole5" HoleDepth 93.98 HoleDiameter 3.5 (= "m3_diam") TipAngle 180
base_feature "Base Feature1"
base_feature "Base Feature1"
base_feature "Base Feature2"
base_feature "Base Feature3"
base_feature "Base Feature4"
base_feature "Base Feature5"
base_feature "Base Feature6"
base_feature "Base Feature7"
base_feature "Base Feature8"
base_feature "Base Feature9"
base_feature "Base Feature10"
base_feature "Base Feature11"
base_feature "Base Feature12"
base_feature "Base Feature13"
base_feature "Base Feature14"
base_feature "Base Feature15"
create_component "CreateComponent1"
create_component "CreateComponent2"
create_component "CreateComponent1"
create_component "CreateComponent1"
create_component "CreateComponent2"
create_component "CreateComponent2"
remove_body "RemoveBody1"
remove_body "RemoveBody1"
remove_body "RemoveBody2"
create_component "CreateComponent3"
remove_body "RemoveBody1"
create_component "CreateComponent3"
remove_body "RemoveBody3"
remove_instance "RemoveInstance1"
create_component "CreateComponent4"
remove_instance "RemoveInstance2"
remove_body "RemoveBody1"
remove_body "RemoveBody4"
create_component "CreateComponent1"
remove_body "RemoveBody2"
remove_body "RemoveBody3"
remove_body "RemoveBody4"
remove_body "RemoveBody6"
remove_instance "RemoveInstance1"
remove_body "RemoveBody7"
remove_body "RemoveBody9"
remove_instance "RemoveInstance1"
remove_body "RemoveBody5"
remove_body "RemoveBody6"
remove_body "RemoveBody1"
remove_body "RemoveBody2"
create_component "CreateComponent5"
remove_instance "RemoveInstance3"
create_component "CreateComponent1"
create_component "CreateComponent2"
create_component "CreateComponent3"
create_component "CreateComponent4"
create_component "CreateComponent5"
create_component "CreateComponent6"
create_component "CreateComponent6"
remove_instance "RemoveInstance1"
create_component "CreateComponent1"
remove_body "RemoveBody5"
create_component "CreateComponent2"
remove_body "RemoveBody6"
create_component "CreateComponent3"
remove_body "RemoveBody7"
create_component "CreateComponent7"
remove_instance "RemoveInstance5"
remove_instance "RemoveInstance2"
create_component "CreateComponent1"
create_component "CreateComponent26"
create_component "CreateComponent2"
create_component "CreateComponent3"
create_component "CreateComponent4"
remove_instance "RemoveInstance1"
remove_instance "RemoveInstance2"
remove_instance "RemoveInstance3"
create_component "CreateComponent7"
remove_body "RemoveBody1"
create_component "CreateComponent8"
remove_body "RemoveBody2"
create_component "CreateComponent9"
remove_body "RemoveBody3"
create_component "CreateComponent10"
remove_body "RemoveBody4"
remove_instance "RemoveInstance8"
remove_instance "RemoveInstance9"
remove_instance "RemoveInstance10"
remove_instance "RemoveInstance11"
remove_body "RemoveBody13"
create_component "CreateComponent1"
remove_body "RemoveBody1"
remove_instance "RemoveInstance14"
create_component "CreateComponent1"
create_component "CreateComponent2"
create_component "CreateComponent13"
create_component "CreateComponent14"
remove_body "RemoveBody14"
remove_body "RemoveBody15"
remove_body "RemoveBody16"
remove_body "RemoveBody17"
remove_body "RemoveBody18"
remove_body "RemoveBody19"
remove_body "RemoveBody20"
remove_body "RemoveBody21"
remove_instance "RemoveInstance15"
remove_body "RemoveBody22"
create_component "CreateComponent15"
remove_body "RemoveBody23"
remove_instance "RemoveInstance16"
remove_body "RemoveBody1"
remove_body "RemoveBody2"
remove_body "RemoveBody3"
remove_body "RemoveBody4"
remove_body "RemoveBody5"
remove_body "RemoveBody24"
remove_body "RemoveBody25"
remove_body "RemoveBody26"
remove_body "RemoveBody27"
remove_body "RemoveBody6"
remove_body "RemoveBody28"
create_component "CreateComponent16"
remove_body "RemoveBody29"
remove_instance "RemoveInstance17"
create_component "CreateComponent17"
remove_body "RemoveBody30"
remove_instance "RemoveInstance18"
remove_body "RemoveBody37"
remove_body "RemoveBody38"
remove_body "RemoveBody39"
remove_instance "RemoveInstance19"
create_component "CreateComponent2"
remove_body "RemoveBody2"

design "Servo Actuator 2.0"
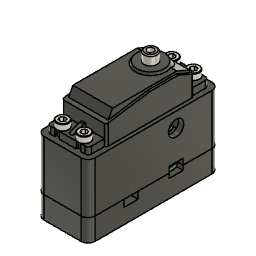
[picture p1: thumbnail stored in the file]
base_feature "Base Feature1"
base_feature "Base Feature1"
base_feature "Base Feature1"
base_feature "Base Feature1"
extrude "Extrude1" add of existing geometry blind 3.556
extrude "Extrude2" add of existing geometry blind 1
sketch "Sketch1" plane through (0, 0, 13.9918) normal (0, 0, -1) x axis (1, 0, 0)
  circle C1 centre (0, -10.25) radius 4
  circle C2 centre (0, -10.25) radius 8.7625
  dimension "d5" = 4.7625
extrude "Extrude1" new body sketch "Sketch1" along normal blind 5.675 (= "0.125 in + 2.5 mm")
extrude "Extrude3" add of existing geometry blind 3.175
combine "Combine1"
extrude "Extrude2" cut of existing geometry blind -4.7
sketch "Sketch2" plane through (0, 0, 24.9956) normal (0, 0, 1) x axis (-1, 0, 0)
  line L1 (0.8395, -12.0586) -> (1.9866, -10.4203)
  line L2 (-1.9866, -10.0797) -> (0.8395, -12.0586)
  line L3 (-0.8395, -8.4414) -> (-1.9866, -10.0797)
  line L4 (1.9866, -10.4203) -> (-0.8395, -8.4414)
  line L5 (-1.9866, -10.0797) -> (-0.8395, -8.4414)
  line L6 (0.8395, -12.0586) -> (-1.9866, -10.0797)
  line L7 (1.9866, -10.4203) -> (0.8395, -12.0586)
  line L8 (-0.8395, -8.4414) -> (1.9866, -10.4203)
  circle C1 centre (0, -10.25) radius 4
split "Split1"
copy_paste_bodies "CutPasteBodies1"
copy_paste_bodies "CutPasteBodies1"
component_from_bodies "Body->Comp1"
extrude "Extrude3" new body of existing geometry blind 2.5
delete_face "DeleteFace1"
component_from_bodies "Body->Comp1"
copy_paste "CutPaste1"
sketch "Sketch1" plane through (0, 0, 0) normal (0, 0, 1) x axis (1, 0, 0)
  line L1 (-7.25, -8.75) -> (7.25, -8.75)
  line L2 (-7.25, 8.75) -> (-7.25, -8.75)
  line L3 (7.25, 8.75) -> (-7.25, 8.75)
  line L4 (7.25, -8.75) -> (7.25, 8.75)
  line L5 (-7.25, 8.75) -> (7.25, -8.75)
  line L6 (7.25, 8.75) -> (-7.25, -8.75)
  line L7 (0, 8.75) -> (0, -8.75)
  line L8 (-2.5, -2.35) -> (2.5, -2.35)
  line L9 (-2.5, 1.45) -> (-2.5, -2.35)
  line L10 (2.5, 1.45) -> (-2.5, 1.45)
  line L11 (2.5, -2.35) -> (2.5, 1.45)
  line L12 (-2.5, 1.45) -> (2.5, -2.35)
  line L13 (2.5, 1.45) -> (-2.5, -2.35)
  line L14 (7.25, -0.45) -> (-7.25, -0.45)
  line L15 (3.75, -8.75) -> (7.25, -5.25)
  line L16 (-3.75, -8.75) -> (-7.25, -5.25)
  arc A1 centre (0, 0.1797) radius 8.5703 clockwise from (-7.25, 4.75) to (7.25, 4.75)
  circle C1 centre (6, -0.45) radius 1.5
  circle C2 centre (-6, -0.45) radius 1.5
  point P6 (0, 0)
  point P1 (0, 0)
  point P7 (0, -8.75)
  point P8 (0, 8.75)
  point P13 (0, -0.45)
  point P14 (-7.25, -0.45)
  point P15 (7.25, -0.45)
  point P16 (7.25, 4.75)
  point P17 (-7.25, 4.75)
  point P19 (7.25, 4.75)
  point P18 (-7.25, 4.75)
  point P21 (7.25, -5.25)
  point P22 (3.75, -8.75)
  point P23 (7.25, -5.25)
  point P24 (3.75, -8.75)
  point P25 (-7.25, -5.25)
  point P26 (-3.75, -8.75)
  point P27 (6, -0.45)
  point P2 (7.25, -8.75)
  point P5 (7.25, 8.75)
  horizontal L1
  perpendicular L1 L2
  parallel L1 L3
  parallel L2 L4
  coincident L5 P6
  coincident L6 P6
  coincident P1 P6
  midpoint L1 P7
  midpoint L3 P8
  horizontal L8
  perpendicular L8 L9
  parallel L8 L10
  parallel L9 L11
  coincident L12 P13
  coincident L13 P13
  coincident L7 P13
  coincident L2 P14
  coincident L4 P15
  perpendicular L4 L14
  coincident P13 L14
  coincident L4 P16
  symmetric L7 P16 P17
  coincident P8 A1
  tangent L3 A1
  coincident P16 P19
  coincident P17 P18
  coincident L4 P21
  coincident L1 P22
  coincident P21 P23
  coincident P22 P24
  symmetric L7 P23 P25
  symmetric L7 P24 P26
  coincident L14 P27
  symmetric L7 C1 C2
  dimension "d1_1" distance P2 P5 = 17.5
  dimension "d2_1" distance L2 L4 = 14.5
  dimension "d3_1" distance L1 L8 = 6.4
  dimension "d4_1" distance L3 L10 = 7.3
  dimension "d5_1" distance L9 L11 = 5
  dimension "d6_1" distance P5 P16 = 4
  dimension "d7_1" distance P2 P21 = 3.5
  dimension "d8_1" distance P2 P22 = 3.5
  dimension "d9_1" diameter C1 = 3
  dimension "d10_1" distance L11 P27 = 3.5 (= "2 mm + 1.5 mm")
extrude "Extrude1" new body sketch "Sketch1" profile of L1 L2 L4 L8 L9 L10 L11 A1 L15 L16 C1 C2 against normal blind 1.7 named "d11_1"
extrude "Extrude2" new body sketch "Sketch1" profile of L8 L9 L10 L11 along normal blind 1.5 named "d13_1"
position "Position1"
position "Position2"
position "Position3"
position "Position4"
copy_paste "CutPaste2"
work_plane "WorkPlane1" AlongDistance -21
split "Split1"
combine "Combine1"
split "Split1"
remove_body "RemoveBody2"
extrude "Extrude1" add of existing geometry blind 2.2
extrude "Extrude2" add of existing geometry blind 1
extrude "Extrude3" cut of existing geometry blind -0.2
extrude "Extrude4" add of existing geometry blind 0.2
work_plane "WorkPlane2"
extrude "Extrude4" cut of existing geometry blind -0.2063 (= "( 2 mm - ( ( 1 / 16 ) * 1 in ) ) / -2")
extrude "Extrude5" cut of existing geometry blind -0.2063 (= "( 2 mm - ( ( 1 / 16 ) * 1 in ) ) / -2")
extrude "Extrude5" add of existing geometry blind 0.2063 (= "( 2 mm - ( ( 1 / 16 ) * 1 in ) ) / 2")
extrude "Extrude6" add of existing geometry blind 0.2063 (= "( 2 mm - ( ( 1 / 16 ) * 1 in ) ) / 2")
sketch "Sketch4" plane through (0, 0, 28) normal (0, 0, -1) x axis (1, 0, 0)
  line L1 (-1.6037, -23.3708) -> (-1.6037, 14.6292)
  line L2 (-0.9037, -30.2208) -> (-0.9037, -24.3248)
  line L3 (2.4963, -31.7208) -> (0.5963, -31.7208)
  line L4 (2.4963, -31.0175) -> (2.4963, -31.7208)
  line L5 (4.4963, -31.7208) -> (4.4963, -31.0175)
  line L6 (12.2963, -31.7208) -> (4.4963, -31.7208)
  line L7 (12.2963, -31.0175) -> (12.2963, -31.7208)
  line L8 (14.2963, -31.7208) -> (14.2963, -31.0175)
  line L9 (16.1963, -31.7208) -> (14.2963, -31.7208)
  line L10 (17.6963, -24.3248) -> (17.6963, -30.2208)
  line L11 (18.3963, 14.6292) -> (18.3963, -23.3708)
  line L12 (17.6963, 21.4792) -> (17.6963, 15.5831)
  line L13 (14.2963, 22.9792) -> (16.1963, 22.9792)
  line L14 (14.2963, 22.2758) -> (14.2963, 22.9792)
  line L15 (12.2963, 22.9792) -> (12.2963, 22.2758)
  line L16 (4.4963, 22.9792) -> (12.2963, 22.9792)
  line L17 (4.4963, 22.2758) -> (4.4963, 22.9792)
  line L18 (2.4963, 22.9792) -> (2.4963, 22.2758)
  line L19 (0.5963, 22.9792) -> (2.4963, 22.9792)
  line L20 (-0.9037, 15.5831) -> (-0.9037, 21.4792)
  line L21 (15.3963, 15.6292) -> (1.3963, 15.6292)
  line L22 (1.3963, 15.6292) -> (15.3963, 15.6292)
  line L23 (8.3963, -2.0612) -> (8.3963, 15.6292)
  line L24 (22.9806, 14.6292) -> (-3.2785, 14.6292)
  arc A1 centre (-0.6037, 14.6292) radius 1 clockwise from (-1.6037, 14.6292) to (-0.9037, 15.5831)
  arc A2 centre (-0.6037, -23.3708) radius 1 clockwise from (-0.9037, -24.3248) to (-1.6037, -23.3708)
  arc A3 centre (0.5963, -30.2208) radius 1.5 clockwise from (0.5963, -31.7208) to (-0.9037, -30.2208)
  arc A4 centre (3.4963, -29.1708) radius 2.1 clockwise from (2.4963, -31.0175) to (4.4963, -31.0175)
  arc A5 centre (13.2963, -29.1708) radius 2.1 clockwise from (12.2963, -31.0175) to (14.2963, -31.0175)
  arc A6 centre (16.1963, -30.2208) radius 1.5 clockwise from (17.6963, -30.2208) to (16.1963, -31.7208)
  arc A7 centre (17.3963, -23.3708) radius 1 clockwise from (18.3963, -23.3708) to (17.6963, -24.3248)
  arc A8 centre (17.3963, 14.6292) radius 1 clockwise from (17.6963, 15.5831) to (18.3963, 14.6292)
  arc A9 centre (16.1963, 21.4792) radius 1.5 clockwise from (16.1963, 22.9792) to (17.6963, 21.4792)
  arc A10 centre (13.2963, 20.4292) radius 2.1 clockwise from (14.2963, 22.2758) to (12.2963, 22.2758)
  arc A11 centre (3.4963, 20.4292) radius 2.1 clockwise from (4.4963, 22.2758) to (2.4963, 22.2758)
  arc A12 centre (0.5963, 21.4792) radius 1.5 clockwise from (-0.9037, 21.4792) to (0.5963, 22.9792)
  circle C1 centre (8.3963, 6.1292) radius 8.5
  point P48 (8.3963, 15.6292)
  point P50 (8.3963, 6.1292)
  midpoint L21 P48
  perpendicular L21 L23
  coincident L23 P50
  perpendicular L1 L24
  tangent C1 L24
  dimension "d32" diameter C1 = 17
  dimension "d33" distance L22 L24 = 1
extrude "Extrude4" new body sketch "Sketch4" profile of C1 along normal blind 27.9908
extrude "Extrude5" add of existing geometry blind 0.5092 (= "41.5 mm - 1.6138110236220502 in")
copy_paste_bodies "CutPasteBodies1"
sketch "Sketch5" plane through (0, 0, 28) normal (0, 0, -1) x axis (1, 0, 0)
  line L1 (-1.6037, -23.3708) -> (-1.6037, 14.6292)
  line L2 (-0.9037, -30.2208) -> (-0.9037, -24.3248)
  line L3 (2.4963, -31.7208) -> (0.5963, -31.7208)
  line L4 (2.4963, -31.0175) -> (2.4963, -31.7208)
  line L5 (4.4963, -31.7208) -> (4.4963, -31.0175)
  line L6 (12.2963, -31.7208) -> (4.4963, -31.7208)
  line L7 (12.2963, -31.0175) -> (12.2963, -31.7208)
  line L8 (14.2963, -31.7208) -> (14.2963, -31.0175)
  line L9 (16.1963, -31.7208) -> (14.2963, -31.7208)
  line L10 (17.6963, -24.3248) -> (17.6963, -30.2208)
  line L11 (18.3963, 14.6292) -> (18.3963, -23.3708)
  line L12 (17.6963, 21.4792) -> (17.6963, 15.5831)
  line L13 (14.2963, 22.9792) -> (16.1963, 22.9792)
  line L14 (14.2963, 22.2758) -> (14.2963, 22.9792)
  line L15 (12.2963, 22.9792) -> (12.2963, 22.2758)
  line L16 (4.4963, 22.9792) -> (12.2963, 22.9792)
  line L17 (4.4963, 22.2758) -> (4.4963, 22.9792)
  line L18 (2.4963, 22.9792) -> (2.4963, 22.2758)
  line L19 (0.5963, 22.9792) -> (2.4963, 22.9792)
  line L20 (-0.9037, 15.5831) -> (-0.9037, 21.4792)
  arc A1 centre (-0.6037, 14.6292) radius 1 clockwise from (-1.6037, 14.6292) to (-0.9037, 15.5831)
  arc A2 centre (-0.6037, -23.3708) radius 1 clockwise from (-0.9037, -24.3248) to (-1.6037, -23.3708)
  arc A3 centre (0.5963, -30.2208) radius 1.5 clockwise from (0.5963, -31.7208) to (-0.9037, -30.2208)
  arc A4 centre (3.4963, -29.1708) radius 2.1 clockwise from (2.4963, -31.0175) to (4.4963, -31.0175)
  arc A5 centre (13.2963, -29.1708) radius 2.1 clockwise from (12.2963, -31.0175) to (14.2963, -31.0175)
  arc A6 centre (16.1963, -30.2208) radius 1.5 clockwise from (17.6963, -30.2208) to (16.1963, -31.7208)
  arc A7 centre (17.3963, -23.3708) radius 1 clockwise from (18.3963, -23.3708) to (17.6963, -24.3248)
  arc A8 centre (17.3963, 14.6292) radius 1 clockwise from (17.6963, 15.5831) to (18.3963, 14.6292)
  arc A9 centre (16.1963, 21.4792) radius 1.5 clockwise from (16.1963, 22.9792) to (17.6963, 21.4792)
  arc A10 centre (13.2963, 20.4292) radius 2.1 clockwise from (14.2963, 22.2758) to (12.2963, 22.2758)
  arc A11 centre (3.4963, 20.4292) radius 2.1 clockwise from (4.4963, 22.2758) to (2.4963, 22.2758)
  arc A12 centre (0.5963, 21.4792) radius 1.5 clockwise from (-0.9037, 21.4792) to (0.5963, 22.9792)
split "Split1"
remove_body "RemoveBody1"
delete_face "DeleteFace1"
delete_face "DeleteFace2"
sketch "Sketch6" plane through (0, 0, 28) normal (0, 0, -1) x axis (1, 0, 0)
  line L1 (-0.9037, -24.3248) -> (17.6963, 15.5831)
  line L2 (-0.9037, 15.5831) -> (17.6963, -24.3248)
  line L3 (-0.8337, -23.6158) -> (17.6263, -23.6158)
  line L4 (-0.8337, 14.8742) -> (-0.8337, -23.6158)
  line L5 (17.6263, 14.8742) -> (-0.8337, 14.8742)
  line L6 (17.6263, -23.6158) -> (17.6263, 14.8742)
  line L7 (-0.8337, 14.8742) -> (17.6263, -23.6158)
  line L8 (17.6263, 14.8742) -> (-0.8337, -23.6158)
  line L9 (-4.0087, 18.0492) -> (-4.0087, -26.7908)
  line L10 (20.8013, 18.0492) -> (-4.0087, 18.0492)
  line L11 (20.8013, -26.7908) -> (20.8013, 18.0492)
  line L12 (-4.0087, -26.7908) -> (20.8013, -26.7908)
  point P2 (17.6963, 15.5831)
  point P6 (17.6963, 15.5831)
  point P4 (-0.9037, -24.3248)
  point P7 (-0.9037, -24.3248)
  point P3 (17.6963, -24.3248)
  point P8 (17.6963, -24.3248)
  point P5 (-0.9037, 15.5831)
  point P9 (-0.9037, 15.5831)
  point P10 (8.3963, -4.3708)
  point P15 (8.3963, -4.3708)
  point P13 (-0.8337, 14.8742)
  point P14 (17.6263, 14.8742)
  point P11 (17.6263, -23.6158)
  coincident P2 P6
  coincident P4 P7
  coincident P3 P8
  coincident P5 P9
  midpoint L1 P10
  horizontal L3
  perpendicular L3 L4
  parallel L3 L5
  parallel L4 L6
  coincident L7 P15
  coincident L8 P15
  coincident P10 P15
  dimension "d38" distance P13 P14 = 18.46
  dimension "d39" distance P11 P14 = 38.49
  dimension "d44" = -3.175 (= "( -1 / 8 ) * 1 in")
split "Split2"
split "Split3"
delete_face "DeleteFace3"
extrude "Extrude1" cut of existing geometry blind -33.02
delete_face "DeleteFace4"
